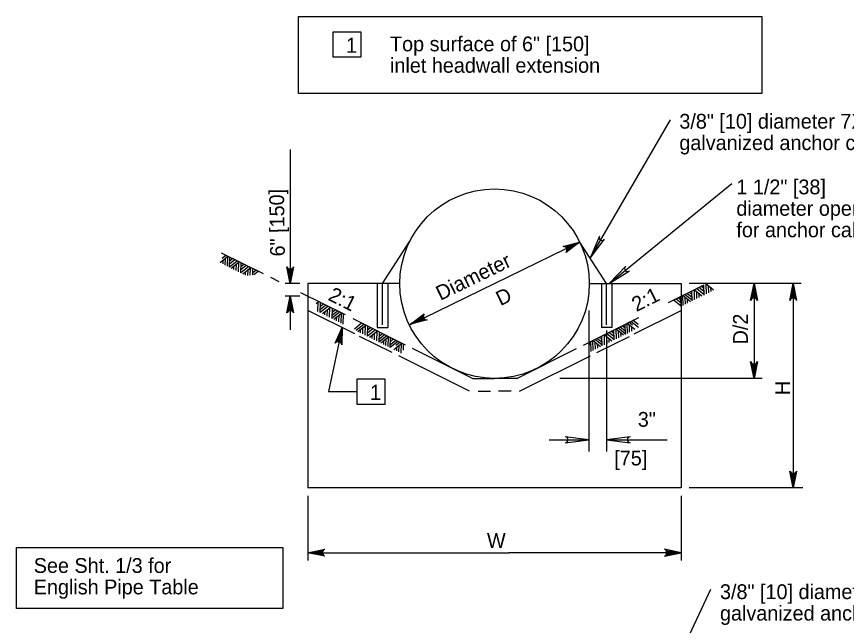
# Model space of a CAD drawing. Extents: x 1083.1 to 1117.1, y 675.4 to 741.4.
# Drawn here: x 1103.78 to 1112.53, y 706.36 to 712.78 of the extents above; entities that cross this region are included whole.
import ezdxf

# ---------------------------------------------------------------- set-up
doc = ezdxf.new("R2010")
doc.units = 0
doc.layers.add('Level 1', color=7, linetype='Continuous')
doc.layers.add('Level 44', color=7, linetype='Continuous')

msp = doc.modelspace()

# ---------------------------------------------------------------- linework, layer by layer
at = {"layer": 'Level 1'}
for p, q in [((1107.1163, 712.6125), (1107.1163, 712.3508)), ((1107.4151, 712.6125), (1107.1163, 712.6125)), ((1107.4151, 712.3508), (1107.4151, 712.6125)), ((1107.1163, 712.3508), (1107.4151, 712.3508)), ((1109.8305, 710.229), (1110.6781, 711.6859)), ((1106.6688, 711.3758), (1106.6688, 709.9606)), ((1110.0317, 709.9606), (1111.3244, 711.0163)), ((1107.6414, 709.9606), (1107.9291, 710.4067)), ((1110.0035, 709.9606), (1109.7158, 710.4067)), ((1109.7198, 710.3982), (1107.9252, 709.5231)), ((1109.5632, 710.3494), (1109.7198, 710.3982)), ((1109.5732, 710.3428), (1109.7198, 710.3982)), ((1109.5822, 710.3311), (1109.7198, 710.3982)), ((1109.5856, 710.3201), (1109.7198, 710.3982)), ((1109.5856, 710.3078), (1109.7198, 710.3982)), ((1105.9282, 710.1833), (1106.0114, 710.2498)), ((1106.3862, 710.0625), (1105.9452, 710.283)), ((1105.9513, 710.2296), (1105.9899, 710.2606)), ((1105.9824, 710.1563), (1105.985, 710.2285)), ((1106.0061, 710.1445), (1106.0093, 710.2476)), ((1106.0275, 710.1337), (1106.0308, 710.2405)), ((1106.0293, 710.1999), (1106.0607, 710.2251)), ((1105.9596, 710.1676), (1105.961, 710.2096)), ((1106.0275, 710.1371), (1106.1084, 710.2013)), ((1106.0284, 710.1678), (1106.0849, 710.2131)), ((1106.0457, 710.1246), (1106.1296, 710.1907)), ((1106.0726, 710.1111), (1106.074, 710.1467)), ((1106.0978, 710.0985), (1106.1002, 710.1675)), ((1106.1226, 710.0861), (1106.1256, 710.1874)), ((1106.1465, 710.0741), (1106.1498, 710.1806)), ((1106.1466, 710.0771), (1106.2276, 710.1418)), ((1106.1477, 710.1102), (1106.2026, 710.1542)), ((1106.1491, 710.1411), (1106.1796, 710.1657)), ((1106.1691, 710.0629), (1106.2526, 710.1293)), ((1106.1968, 710.0491), (1106.1979, 710.0858)), ((1106.2213, 710.0457), (1106.2232, 710.1061)), ((1106.2465, 710.0496), (1106.2487, 710.1261)), ((1106.2729, 710.0538), (1106.2748, 710.1181)), ((1106.2737, 710.0774), (1106.3052, 710.103)), ((1106.2839, 710.0556), (1106.3288, 710.0911)), ((1106.6463, 710.1209), (1106.6688, 709.9606)), ((1106.6574, 710.1155), (1106.6688, 709.9606)), ((1106.6935, 710.1227), (1106.6688, 709.9606)), ((1106.6832, 710.1166), (1106.6688, 709.9606)), ((1106.6688, 710.1138), (1106.6688, 709.9606)), ((1106.2727, 710.0466), (1106.2742, 710.0479)), ((1106.551, 709.9801), (1106.4629, 710.0241)), ((1106.7711, 709.9606), (1106.6145, 709.9606)), ((1106.8544, 709.9606), (1106.8544, 707.8079)), ((1107.8239, 709.9606), (1106.8544, 709.9606)), ((1107.5865, 709.9606), (1107.5865, 709.4974)), ((1107.6414, 709.5273), (1107.6414, 709.9606)), ((1107.6963, 709.9606), (1107.6963, 709.4974)), ((1109.821, 709.9606), (1110.7906, 709.9606)), ((1109.9486, 709.9606), (1109.9486, 709.4974)), ((1110.0035, 709.5273), (1110.0035, 709.9606)), ((1110.0584, 709.9606), (1110.0584, 709.4974)), ((1110.6558, 709.761), (1111.0246, 709.9454)), ((1110.7906, 709.9606), (1110.7906, 707.8079)), ((1112.0546, 709.9606), (1110.8738, 709.9606)), ((1110.9064, 709.7781), (1110.9032, 709.8846)), ((1111.0089, 709.8294), (1110.9255, 709.8957)), ((1110.9322, 709.791), (1110.9293, 709.8926)), ((1111.0314, 709.8436), (1110.9505, 709.9082)), ((1111.0303, 709.8766), (1110.9755, 709.9207)), ((1111.029, 709.9075), (1110.9985, 709.9322)), ((1111.0315, 709.8406), (1111.0283, 709.9471)), ((1111.1323, 709.891), (1111.0485, 709.9572)), ((1111.0554, 709.8526), (1111.0525, 709.9539)), ((1111.0802, 709.865), (1111.0779, 709.9339)), ((1111.1054, 709.8775), (1111.1041, 709.9131)), ((1111.5332, 709.7985), (1111.5579, 709.9606)), ((1111.5436, 709.8046), (1111.5579, 709.9606)), ((1111.5579, 709.9606), (1111.5579, 709.2748)), ((1111.5579, 709.8075), (1111.5579, 709.9606)), ((1111.5693, 709.8058), (1111.5579, 709.9606)), ((1111.5804, 709.8004), (1111.5579, 709.9606)), ((1111.9466, 709.7985), (1111.9713, 709.9606)), ((1111.9569, 709.8046), (1111.9713, 709.9606)), ((1111.9713, 709.9606), (1111.9713, 708.7602)), ((1111.9713, 709.8075), (1111.9713, 709.9606)), ((1111.9827, 709.8058), (1111.9713, 709.9606)), ((1111.9937, 709.8004), (1111.9713, 709.9606)), ((1106.7711, 709.8284), (1106.6145, 709.8284)), ((1106.6439, 709.6662), (1106.6688, 709.8284)), ((1106.6543, 709.6724), (1106.6688, 709.8284)), ((1106.6688, 709.8284), (1106.6688, 709.4736)), ((1106.6688, 709.6752), (1106.6688, 709.8284)), ((1106.6801, 709.6736), (1106.6688, 709.8284)), ((1106.6912, 709.6681), (1106.6688, 709.8284)), ((1107.2513, 709.63), (1106.7815, 709.8648)), ((1110.7904, 709.7234), (1110.7096, 709.7878)), ((1110.7895, 709.7541), (1110.7329, 709.7995)), ((1110.7886, 709.7863), (1110.7571, 709.8116)), ((1110.7904, 709.7201), (1110.7871, 709.8269)), ((1110.8898, 709.7697), (1110.8065, 709.8363)), ((1110.8118, 709.7308), (1110.8086, 709.834)), ((1110.8667, 709.816), (1110.828, 709.8471)), ((1110.8355, 709.7426), (1110.8329, 709.8149)), ((1110.9053, 709.8131), (1110.8492, 709.8576)), ((1110.8583, 709.7541), (1110.8568, 709.796)), ((1110.9061, 709.7846), (1110.8667, 709.816)), ((1110.9044, 709.8439), (1110.8728, 709.8695)), ((1110.9569, 709.8033), (1110.9549, 709.8724)), ((1110.9813, 709.8156), (1110.9801, 709.8522)), ((1106.9405, 709.7504), (1106.9676, 709.7718)), ((1106.9606, 709.6672), (1106.9636, 709.7685)), ((1106.9845, 709.6552), (1106.9878, 709.7616)), ((1106.9847, 709.6582), (1107.0657, 709.7228)), ((1106.9858, 709.6912), (1107.0407, 709.7352)), ((1106.9871, 709.7221), (1107.0176, 709.7468)), ((1107.0071, 709.644), (1107.0906, 709.7103)), ((1107.0839, 709.6056), (1107.0867, 709.7072)), ((1107.1097, 709.5926), (1107.1129, 709.6992)), ((1107.3497, 709.4299), (1106.8544, 709.6775)), ((1107.0348, 709.6301), (1107.036, 709.6668)), ((1107.0593, 709.6179), (1107.0612, 709.6871)), ((1107.1099, 709.5992), (1107.1494, 709.6306)), ((1107.1108, 709.6277), (1107.1669, 709.6722)), ((1107.1117, 709.6585), (1107.1432, 709.6841)), ((1107.1263, 709.5843), (1107.2096, 709.6508)), ((1107.1494, 709.6306), (1107.1881, 709.6616)), ((1107.1806, 709.5572), (1107.1832, 709.6294)), ((1107.2043, 709.5454), (1107.2075, 709.6486)), ((1107.2258, 709.5346), (1107.2291, 709.6414)), ((1108.0718, 709.6229), (1107.9377, 709.5326)), ((1109.8175, 709.6766), (1109.8175, 708.1921)), ((1110.2952, 709.4299), (1110.7906, 709.6775)), ((1107.1577, 709.5686), (1107.1592, 709.6105)), ((1107.8841, 709.3136), (1107.332, 709.5896)), ((1107.3442, 709.4847), (1107.4201, 709.5456)), ((1107.3627, 709.4696), (1107.4435, 709.5339)), ((1108.0718, 709.6106), (1107.9377, 709.5326)), ((1108.0753, 709.5996), (1107.9377, 709.5326)), ((1108.0842, 709.588), (1107.9377, 709.5326)), ((1108.0942, 709.5813), (1107.9377, 709.5326)), ((1109.7608, 709.3136), (1110.3442, 709.6052)), ((1110.2018, 709.426), (1110.1985, 709.5327)), ((1110.3012, 709.4756), (1110.2179, 709.5421)), ((1110.2233, 709.4366), (1110.2201, 709.5398)), ((1110.2781, 709.5218), (1110.2394, 709.5529)), ((1110.3387, 709.4977), (1110.258, 709.5621)), ((1110.3378, 709.5285), (1110.2812, 709.5738)), ((1107.1558, 709.3444), (1107.2144, 709.4976)), ((1107.1673, 709.3481), (1107.2144, 709.4976)), ((1107.1819, 709.3479), (1107.2144, 709.4976)), ((1107.1926, 709.3438), (1107.2144, 709.4976)), ((1107.2023, 709.3362), (1107.2144, 709.4976)), ((1107.3809, 709.4571), (1107.4647, 709.5233)), ((1107.4077, 709.4436), (1107.4092, 709.4792)), ((1107.433, 709.4311), (1107.4353, 709.5)), ((1107.4577, 709.4187), (1107.4606, 709.52)), ((1107.4816, 709.4067), (1107.4848, 709.5131)), ((1107.4817, 709.4097), (1107.5628, 709.4743)), ((1107.4827, 709.4427), (1107.5377, 709.4868)), ((1107.4842, 709.4736), (1107.5147, 709.4983)), ((1107.5042, 709.3955), (1107.5877, 709.4617)), ((1107.5562, 709.3694), (1107.5583, 709.4385)), ((1107.581, 709.3571), (1107.5838, 709.4586)), ((1107.5865, 709.4974), (1107.6963, 709.4974)), ((1107.6068, 709.3441), (1107.61, 709.4506)), ((1110.0584, 709.4974), (1109.9486, 709.4974)), ((1110.0035, 709.4675), (1110.0035, 708.1921)), ((1110.0817, 709.4025), (1110.0267, 709.4465)), ((1110.0803, 709.4333), (1110.0498, 709.4581)), ((1110.0828, 709.3665), (1110.0797, 709.4729)), ((1110.1836, 709.4169), (1110.0997, 709.4831)), ((1110.1067, 709.3785), (1110.1037, 709.4797)), ((1110.2018, 709.4293), (1110.1209, 709.4936)), ((1110.1314, 709.3908), (1110.1292, 709.4597)), ((1110.2009, 709.4601), (1110.1443, 709.5053)), ((1110.1567, 709.4034), (1110.1553, 709.439)), ((1110.2, 709.4921), (1110.1685, 709.5174)), ((1110.247, 709.4485), (1110.2444, 709.5207)), ((1110.2698, 709.4599), (1110.2682, 709.5018)), ((1107.7428, 709.2334), (1107.4003, 709.4046)), ((1107.5318, 709.3816), (1107.533, 709.4183)), ((1107.6071, 709.3507), (1107.6464, 709.3821)), ((1107.6078, 709.3792), (1107.6639, 709.4237)), ((1107.6088, 709.41), (1107.6402, 709.4356)), ((1107.6233, 709.3358), (1107.7067, 709.4024)), ((1107.6464, 709.3821), (1107.6852, 709.4131)), ((1107.6548, 709.3201), (1107.6563, 709.3621)), ((1107.6777, 709.3086), (1107.6802, 709.3809)), ((1107.7013, 709.2968), (1107.7045, 709.4001)), ((1107.7227, 709.2862), (1107.7261, 709.393)), ((1107.7227, 709.2895), (1107.8036, 709.3539)), ((1107.7237, 709.3202), (1107.7803, 709.3655)), ((1107.7247, 709.3524), (1107.7561, 709.3776)), ((1109.8417, 709.246), (1109.8383, 709.3527)), ((1109.941, 709.2956), (1109.8578, 709.3621)), ((1109.8632, 709.2567), (1109.8599, 709.3598)), ((1109.9179, 709.3418), (1109.8793, 709.3729)), ((1109.9566, 709.339), (1109.9005, 709.3835)), ((1109.9022, 709.2334), (1110.2447, 709.4046)), ((1109.9557, 709.3697), (1109.9241, 709.3953)), ((1109.9577, 709.3039), (1109.9544, 709.4105)), ((1110.0602, 709.3552), (1109.9768, 709.4216)), ((1109.9834, 709.3168), (1109.9806, 709.4185)), ((1110.0828, 709.3695), (1110.0017, 709.434)), ((1110.0082, 709.3291), (1110.0062, 709.3983)), ((1110.0326, 709.3414), (1110.0314, 709.3781)), ((1107.7603, 709.2674), (1107.8436, 709.3338)), ((1107.7834, 709.3136), (1107.8221, 709.3446)), ((1107.7917, 709.2517), (1107.7932, 709.2936)), ((1107.8145, 709.2403), (1107.8171, 709.3125)), ((1107.8382, 709.2285), (1107.8414, 709.3316)), ((1107.8609, 709.2575), (1107.863, 709.3245)), ((1108.5886, 708.9612), (1107.9571, 709.2771)), ((1109.0563, 708.9612), (1109.6879, 709.2771)), ((1109.8398, 709.3121), (1109.8083, 709.3374)), ((1109.8868, 709.2686), (1109.8843, 709.3406)), ((1109.9097, 709.28), (1109.9082, 709.3218)), ((1109.9573, 709.3105), (1109.9179, 709.3418)), ((1111.5579, 709.2748), (1111.5579, 708.9612)), ((1108.558, 708.8256), (1107.8121, 709.1986)), ((1109.0869, 708.8256), (1109.8328, 709.1986)), ((1111.5355, 709.1215), (1111.5579, 708.9612)), ((1111.5467, 709.1161), (1111.5579, 708.9612)), ((1111.5828, 709.1233), (1111.5579, 708.9612)), ((1111.5723, 709.1172), (1111.5579, 708.9612)), ((1111.5579, 709.1144), (1111.5579, 708.9612)), ((1107.3692, 708.9532), (1107.3692, 708.6916)), ((1107.6681, 708.9532), (1107.3692, 708.9532)), ((1107.6681, 708.6916), (1107.6681, 708.9532)), ((1108.5886, 708.9612), (1108.8225, 708.9612)), ((1109.0563, 708.9612), (1108.8225, 708.9612)), ((1111.643, 708.9612), (1109.5098, 708.9612)), ((1108.6486, 708.8256), (1108.7815, 708.8256)), ((1108.9964, 708.8256), (1108.8634, 708.8256)), ((1111.9713, 708.7602), (1111.9713, 707.8079)), ((1107.3692, 708.6916), (1107.6681, 708.6916)), ((1109.3967, 708.3146), (1109.8175, 708.3146)), ((1110.0035, 708.3146), (1110.6437, 708.3146)), ((1111.9489, 707.9681), (1111.9713, 707.8079)), ((1111.96, 707.9627), (1111.9713, 707.8079)), ((1111.9961, 707.97), (1111.9713, 707.8079)), ((1111.9858, 707.9639), (1111.9713, 707.8079)), ((1111.9713, 707.9611), (1111.9713, 707.8079)), ((1110.7906, 707.8079), (1106.8544, 707.8079)), ((1112.0716, 707.8079), (1110.8738, 707.8079)), ((1106.8544, 707.7246), (1106.8544, 707.0412)), ((1110.7906, 707.7246), (1110.7906, 707.0412)), ((1103.7833, 706.537), (1103.7833, 707.1795)), ((1103.7833, 707.1795), (1106.5913, 707.1795)), ((1106.5913, 707.1795), (1106.5913, 706.537)), ((1107.0147, 707.1469), (1106.8544, 707.1245)), ((1107.0093, 707.1358), (1106.8544, 707.1245)), ((1106.8544, 707.1245), (1108.9719, 707.1245)), ((1107.0076, 707.1245), (1106.8544, 707.1245)), ((1107.0104, 707.1101), (1106.8544, 707.1245)), ((1107.0165, 707.0997), (1106.8544, 707.1245)), ((1110.7906, 707.1245), (1108.9719, 707.1245)), ((1110.6284, 707.0997), (1110.7906, 707.1245)), ((1110.6303, 707.1469), (1110.7906, 707.1245)), ((1110.6346, 707.1101), (1110.7906, 707.1245)), ((1110.6357, 707.1358), (1110.7906, 707.1245)), ((1110.6374, 707.1245), (1110.7906, 707.1245)), ((1110.3524, 705.1397), (1111.1038, 706.7406)), ((1106.5913, 706.537), (1103.7833, 706.537))]:
    msp.add_line(p, q, dxfattribs=at)
msp.add_lwpolyline([(1106.757, 712.7751), (1111.6396, 712.7751), (1111.6396, 711.9657), (1106.757, 711.9657)], close=True, dxfattribs=at)
for points in [[(1109.5452, 710.3525), (1109.7198, 710.3982), (1109.5763, 710.2888)], [(1106.7042, 710.1376), (1106.6688, 709.9606), (1106.6333, 710.1376)], [(1111.5226, 709.7836), (1111.5579, 709.9606), (1111.5933, 709.7836)], [(1111.9359, 709.7836), (1111.9713, 709.9606), (1112.0068, 709.7836)], [(1106.6333, 709.6514), (1106.6688, 709.8284), (1106.7042, 709.6514)], [(1108.1122, 709.5783), (1107.9377, 709.5326), (1108.0812, 709.6419)], [(1107.2144, 709.4976), (1107.0712, 708.8224), (1107.3692, 708.8224)], [(1107.1422, 709.3321), (1107.2144, 709.4976), (1107.2114, 709.317)], [(1111.5933, 709.1382), (1111.5579, 708.9612), (1111.5226, 709.1382)], [(1112.0068, 707.9849), (1111.9713, 707.8079), (1111.9359, 707.9849)], [(1107.0314, 707.0891), (1106.8544, 707.1245), (1107.0314, 707.1599)], [(1110.6136, 707.0891), (1110.7906, 707.1245), (1110.6136, 707.1599)]]:
    msp.add_lwpolyline(points, dxfattribs=at)
for centre, start, end in [((1109.5479, 710.3143), 318.08186, 93.90799), ((1106.6687, 710.1519), 202.08782, 337.91395), ((1111.558, 709.7693), 22.08782, 157.91395), ((1111.9714, 709.7693), 22.08782, 157.91395), ((1106.6688, 709.6371), 22.08782, 157.91395), ((1108.1096, 709.6164), 138.08184, 273.90797), ((1107.1739, 709.3106), 9.84921, 145.67534), ((1111.5579, 709.1525), 202.08782, 337.91395), ((1111.9713, 707.9992), 202.08782, 337.91395), ((1107.0457, 707.1246), 112.08782, 247.91395), ((1110.5993, 707.1246), 292.08605, 67.91218)]:
    msp.add_arc(centre, 0.0382, start, end, dxfattribs=at)
msp.add_ellipse((1108.8225, 709.9606), major_axis=(0.9986, 0), ratio=0.999895, dxfattribs=at)
at = {"layer": 'Level 44'}
for p, q in [((1109.9292, 710.4608), (1109.8305, 710.229)), ((1109.8305, 710.229), (1109.9832, 710.4294)), ((1110.2055, 710.143), (1110.0317, 709.9606)), ((1110.0317, 709.9606), (1110.2451, 710.0946)), ((1109.8175, 708.3146), (1109.5675, 708.3458)), ((1109.5675, 708.2833), (1109.8175, 708.3146)), ((1110.2535, 708.3458), (1110.0035, 708.3146)), ((1110.0035, 708.3146), (1110.2535, 708.2833))]:
    msp.add_line(p, q, dxfattribs=at)
for centre, start, end in [((1109.9562, 710.4451), 149.81065, 329.81065), ((1110.2253, 710.1188), 129.23526, 309.23526), ((1109.5675, 708.3146), 270, 90), ((1110.2535, 708.3146), 90, 270)]:
    msp.add_arc(centre, 0.0312, start, end, dxfattribs=at)

# ---------------------------------------------------------------- texts
at = {"layer": 'Level 1'}
for s, height, p in [('1', 0.16, (1107.2551, 712.3932)), ('Top surface of 6" [150]', 0.156, (1107.7205, 712.4092)), ('inlet headwall extension  ', 0.156, (1107.7205, 712.1832)), ('3/8" [10] diameter 7X19', 0.156, (1110.7709, 711.5939)), ('galvanized anchor cable', 0.156, (1110.7709, 711.3679)), ('1 1/2" [38]', 0.156, (1111.3721, 710.9018)), ('diameter opening', 0.156, (1111.3721, 710.6758)), ('for anchor cable', 0.156, (1111.3721, 710.4498)), ('1', 0.16, (1107.5081, 708.734)), ('3"', 0.156, (1110.3328, 708.4515)), ('[75]', 0.156, (1110.0847, 708.044)), ('W', 0.156, (1108.7426, 707.1743)), ('3/8" [10] diameter 7X19', 0.156, (1111.1993, 706.6352)), ('galvanized anchor cable', 0.156, (1111.1993, 706.4092))]:
    msp.add_text(s, height=height, dxfattribs=at).set_placement(p)
for s, rotation, p in [('6" [150]', 90.84991, (1106.6127, 710.2481)), ('Diameter', 25.9977, (1108.2521, 709.7781)), ('2:1', 333.43737, (1107.0567, 709.7924)), ('D', 25.9977, (1108.8851, 709.7219)), ('2:1', 26.56263, (1110.3182, 709.6596)), ('D/2', 90.00001, (1111.4931, 709.3196)), ('H', 90.00001, (1111.9372, 708.7852)), ('See Sht. 1/3 for ', 0, (1103.9643, 706.9113)), ('English Pipe Table', 0, (1103.9643, 706.6853))]:
    msp.add_text(s, height=0.156, rotation=rotation, dxfattribs=at).set_placement(p)

doc.saveas('drawing.dxf')
